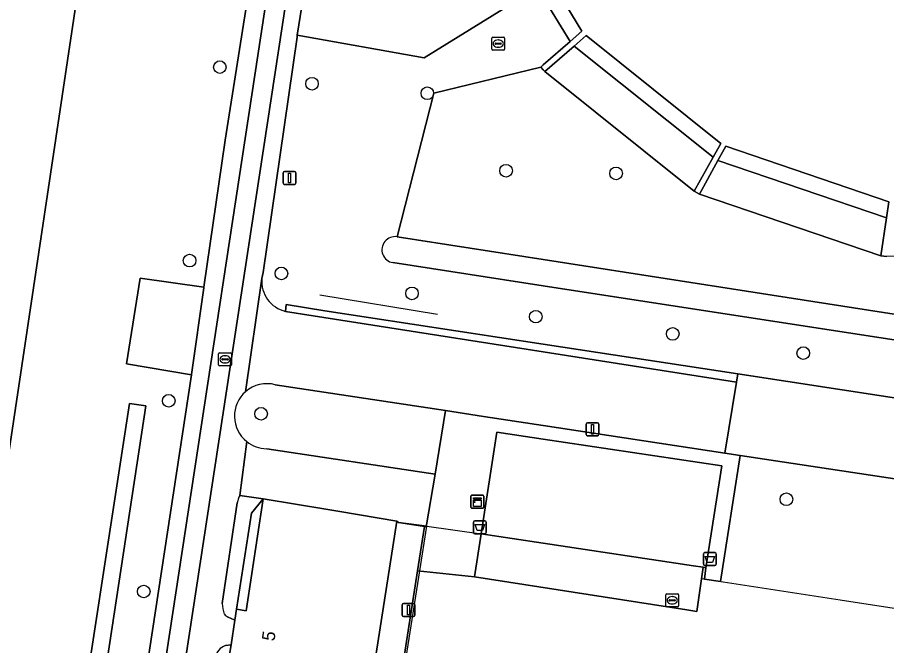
# Model space of a CAD drawing. Extents: x 161090 to 161692, y 379509 to 380907.
# Drawn here: x 161459.2 to 161526.6, y 380261.3 to 380310 of the extents above; entities that cross this region are included whole.
import ezdxf

# ---------------------------------------------------------------- set-up
doc = ezdxf.new("R2010")
doc.units = 0
for name, color, linetype in [('IMGEO_Afvalbak', 7, 'Continuous'), ('IMGEO_Boom', 7, 'Continuous'), ('IMGEO_Greppel_droge_sloot', 7, 'Continuous'), ('IMGEO_Groenvoorziening', 7, 'Continuous'), ('IMGEO_Hek', 7, 'Continuous'), ('IMGEO_Kast', 7, 'Continuous'), ('IMGEO_Lichtmast', 7, 'Continuous'), ('IMGEO_Pand', 7, 'Continuous'), ('IMGEO_Pand_nummerreeks', 7, 'Continuous'), ('IMGEO_Parkeervlak_open', 7, 'Continuous'), ('IMGEO_Rijbaan_lokaal_gesloten', 7, 'Continuous'), ('IMGEO_Rijbaan_lokaal_open', 7, 'Continuous'), ('IMGEO_Rioolput', 7, 'Continuous'), ('IMGEO_Terreindeel_gesloten', 7, 'Continuous'), ('IMGEO_Voetpad_halfverhard', 7, 'Continuous'), ('IMGEO_Voetpad_open', 7, 'Continuous'), ('IMGEO_Waterleidingput', 7, 'Continuous')]:
    doc.layers.add(name, color=color, linetype=linetype)

msp = doc.modelspace()

# ---------------------------------------------------------------- linework, layer by layer
at = {"layer": 'IMGEO_Afvalbak'}
for p, q in [((161494.677, 380270.994), (161495.467, 380270.994)), ((161495.467, 380270.994), (161494.677, 380270.994)), ((161494.577, 380270.094), (161494.577, 380270.894)), ((161494.577, 380270.894), (161494.577, 380270.094)), ((161495.567, 380270.894), (161495.567, 380270.094)), ((161495.567, 380270.094), (161495.567, 380270.894)), ((161495.467, 380269.994), (161494.677, 380269.994)), ((161494.677, 380269.994), (161495.467, 380269.994)), ((161512.428, 380267.629), (161512.428, 380268.429)), ((161512.428, 380268.429), (161512.428, 380267.629)), ((161512.528, 380268.529), (161513.318, 380268.529)), ((161513.318, 380268.529), (161512.528, 380268.529)), ((161513.418, 380268.429), (161513.418, 380267.629)), ((161513.418, 380267.629), (161513.418, 380268.429)), ((161513.318, 380267.529), (161512.528, 380267.529)), ((161512.528, 380267.529), (161513.318, 380267.529))]:
    msp.add_line(p, q, dxfattribs=at)
for points in [[(161494.72, 380270.708), (161495.424, 380270.708), (161495.275, 380270.238), (161494.869, 380270.238), (161494.72, 380270.708)], [(161512.571, 380268.243), (161513.275, 380268.243), (161513.126, 380267.773), (161512.72, 380267.773), (161512.571, 380268.243)]]:
    msp.add_lwpolyline(points, dxfattribs=at)
for centre, start, end in [((161494.677, 380270.894), 90, 180), ((161494.677, 380270.894), 90, 180), ((161495.467, 380270.894), 0, 90), ((161495.467, 380270.894), 360, 90), ((161494.677, 380270.094), 180, 270), ((161494.677, 380270.094), 180, 270), ((161495.467, 380270.094), 270, 0), ((161495.467, 380270.094), 270, 0), ((161512.528, 380268.429), 90, 180), ((161512.528, 380268.429), 90, 180), ((161513.318, 380268.429), 0, 90), ((161513.318, 380268.429), 360, 90), ((161512.528, 380267.629), 180, 270), ((161512.528, 380267.629), 180, 270), ((161513.318, 380267.629), 270, 0), ((161513.318, 380267.629), 270, 0)]:
    msp.add_arc(centre, 0.1, start, end, dxfattribs=at)
at = {"layer": 'IMGEO_Boom'}
for centre in [(161474.898, 380306.17), (161482.053, 380304.882), (161490.999, 380304.148), (161497.111, 380298.137), (161505.645, 380297.93), (161472.554, 380291.168), (161479.68, 380290.173), (161489.81, 380288.629), (161499.416, 380286.823), (161510.042, 380285.49), (161520.172, 380283.997), (161470.934, 380280.302), (161478.097, 380279.294), (161518.864, 380272.671), (161468.994, 380265.516)]:
    msp.add_circle(centre, 0.489, dxfattribs=at)
at = {"layer": 'IMGEO_Greppel_droge_sloot'}
for points in [[(161500, 380291.251), (161488.653, 380293.015)], [(161488.331, 380291.011), (161500, 380289.216), (161574.117, 380277.813), (161575.323, 380279.543), (161566.255, 380280.953), (161500, 380291.251)]]:
    msp.add_lwpolyline(points, dxfattribs=at)
msp.add_lwpolyline([(161469.146, 380279.911), (161467.896, 380280.089), (161463.253, 380250), (161459.495, 380225.647), (161460.876, 380225.356), (161464.612, 380250)], close=True, dxfattribs=at)
msp.add_arc((161488.491, 380292.013), 1.015, 80.8161, 260.92753, dxfattribs=at)
at = {"layer": 'IMGEO_Groenvoorziening'}
for points in [[(161468.714, 380289.805), (161473.666, 380289.12), (161475.319, 380300.52), (161477.293, 380313.127), (161481.572, 380340.98), (161476.723, 380344.754), (161468.564, 380345.931), (161467.674, 380339.759), (161468.027, 380339.705), (161454.566, 380250), (161452.226, 380234.4), (161452.191, 380234.169), (161446.05, 380235.084), (161445.627, 380235.147), (161445.404, 380233.707), (161445.183, 380231.716), (161459.211, 380229.466), (161458.539, 380225.11), (161462.153, 380224.392)], [(161491.515, 380304.148), (161499.803, 380306.171), (161500, 380306.343), (161502.074, 380308.157), (161500, 380311.586), (161499.542, 380312.343), (161490.761, 380306.887), (161480.908, 380308.64), (161480.887, 380308.503), (161478.257, 380290.258), (161478.163, 380289.777)], [(161488.653, 380293.015), (161491.515, 380304.148)], [(161480.007, 380287.232), (161480.042, 380287.763), (161483.038, 380287.288), (161500, 380284.691), (161515.085, 380282.382), (161571.082, 380273.823), (161574.117, 380277.813), (161500, 380289.216), (161488.331, 380291.011)], [(161463.827, 380225.238), (161464.029, 380226.403), (161465.207, 380233.179), (161472.691, 380282.325), (161467.654, 380283.17), (161468.714, 380289.805)], [(161492.398, 380279.538), (161479.202, 380281.544)], [(161478.535, 380276.59), (161491.599, 380274.601), (161492.398, 380279.538)], [(161571.501, 380267.574), (161515.278, 380276.061), (161513.755, 380266.304), (161512.509, 380266.485), (161512.618, 380267.36), (161512.415, 380267.391), (161512.279, 380266.508), (161511.902, 380263.976), (161511.145, 380264.094), (161494.657, 380266.645), (161490.25, 380267.131), (161487.578, 380250), (161486.942, 380245.925), (161484.775, 380246.307), (161476.761, 380247.535), (161466.509, 380179.329)], [(161476.248, 380272.398), (161475.082, 380264.596)], [(161477.368, 380271.592), (161478.255, 380272.694), (161476.447, 380272.956)], [(161475.555, 380263.529), (161476.007, 380263.315), (161476.066, 380263.282), (161476.2, 380264.154), (161477.368, 380271.592)], [(161474.092, 380248.508), (161473.892, 380248.836), (161475.658, 380260.635), (161475.772, 380261.375), (161475.343, 380261.323)]]:
    msp.add_lwpolyline(points, dxfattribs=at)
for points in [[(161513.173, 380299.178), (161502.387, 380307.807), (161500.116, 380305.828), (161511.708, 380296.554)], [(161541.506, 380291.776), (161526.645, 380291.478), (161526.188, 380291.549), (161512.11, 380296.325), (161511.708, 380296.554), (161500.116, 380305.828), (161500, 380305.955), (161499.803, 380306.171), (161491.515, 380304.148), (161488.653, 380293.015), (161500, 380291.251), (161566.255, 380280.953), (161556.212, 380297.498), (161555.81, 380297.247), (161541.96, 380291.864)], [(161526.632, 380294.498), (161513.542, 380298.93), (161512.11, 380296.325), (161526.188, 380291.549)], [(161515.085, 380282.382), (161500, 380284.691), (161483.038, 380287.288), (161480.042, 380287.763), (161480.007, 380287.232), (161500, 380284.102), (161514.984, 380281.757)], [(161463.253, 380250), (161467.896, 380280.089), (161469.146, 380279.911), (161464.612, 380250), (161460.876, 380225.356), (161459.495, 380225.647)], [(161478.255, 380272.694), (161477.368, 380271.592), (161476.2, 380264.154), (161476.94, 380264.03)]]:
    msp.add_lwpolyline(points, close=True, dxfattribs=at)
for centre, radius, start, end in [((161488.491, 380292.013), 1.015, 80.8161, 260.92753), ((161480.546, 380289.563), 2.393, 174.87056, 256.98046), ((161478.553, 380279.11), 2.519, 75.08028, 131.20974), ((161478.554, 380279.11), 2.519, 131.2084, 231.40089), ((161478.555, 380279.109), 2.519, 231.3763, 269.55462), ((161478.34, 380271.966), 2.136, 152.40098, 168.34342), ((161477.584, 380264.669), 2.503, 181.6754, 201.05116), ((161475.707, 380264.038), 0.531, 210.32108, 253.41394), ((161475.716, 380260.18), 1.202, 108.0641, 168.98902)]:
    msp.add_arc(centre, radius, start, end, dxfattribs=at)
at = {"layer": 'IMGEO_Hek'}
for points in [[(161467.654, 380283.17), (161468.714, 380289.805)], [(161482.653, 380288.518), (161491.78, 380287.023)], [(161487.042, 380245.645), (161490.407, 380267.114), (161490.951, 380270.588)], [(161490.951, 380270.588), (161488.77, 380270.861)], [(161490.951, 380270.588), (161495.182, 380269.995)], [(161512.279, 380266.508), (161512.415, 380267.391)], [(161574.717, 380256.895), (161523.039, 380264.851), (161512.279, 380266.508)], [(161512.509, 380266.485), (161513.755, 380266.304)]]:
    msp.add_lwpolyline(points, dxfattribs=at)
at = {"layer": 'IMGEO_Kast'}
for p, q in [((161494.376, 380272.058), (161494.376, 380272.899)), ((161494.376, 380272.899), (161494.376, 380272.058)), ((161494.451, 380272.983), (161495.292, 380272.983)), ((161495.292, 380272.983), (161494.451, 380272.983)), ((161495.376, 380272.908), (161495.376, 380272.067)), ((161495.376, 380272.067), (161495.376, 380272.908)), ((161495.301, 380271.983), (161494.46, 380271.983)), ((161494.46, 380271.983), (161495.301, 380271.983))]:
    msp.add_line(p, q, dxfattribs=at)
for points in [[(161494.571, 380272.773), (161495.171, 380272.773), (161495.171, 380272.688), (161494.571, 380272.688), (161494.571, 380272.773)], [(161494.571, 380272.598), (161495.171, 380272.598), (161495.171, 380272.109), (161494.571, 380272.109), (161494.571, 380272.598)]]:
    msp.add_lwpolyline(points, dxfattribs=at)
msp.add_circle((161494.655, 380272.447), 0.0377, dxfattribs=at)
for centre, start, end in [((161494.454, 380272.905), 92.4484, 184.28452), ((161494.454, 380272.905), 92.4484, 184.28452), ((161495.298, 380272.905), 2.4484, 94.28452), ((161495.298, 380272.905), 2.4484, 94.28452), ((161494.454, 380272.061), 182.4484, 274.28452), ((161494.454, 380272.061), 182.4484, 274.28452), ((161495.298, 380272.061), 272.4484, 4.28452), ((161495.298, 380272.061), 272.4484, 4.28452)]:
    msp.add_arc(centre, 0.0779, start, end, dxfattribs=at)
at = {"layer": 'IMGEO_Lichtmast'}
for p, q in [((161479.813, 380297.181), (161479.813, 380297.981)), ((161479.813, 380297.981), (161479.813, 380297.181)), ((161479.913, 380298.081), (161480.703, 380298.081)), ((161480.703, 380298.081), (161479.913, 380298.081)), ((161480.803, 380297.981), (161480.803, 380297.181)), ((161480.803, 380297.181), (161480.803, 380297.981)), ((161480.703, 380297.081), (161479.913, 380297.081)), ((161479.913, 380297.081), (161480.703, 380297.081)), ((161503.324, 380277.697), (161503.324, 380278.497)), ((161503.324, 380278.497), (161503.324, 380277.697)), ((161503.424, 380278.597), (161504.214, 380278.597)), ((161504.214, 380278.597), (161503.424, 380278.597)), ((161504.314, 380278.497), (161504.314, 380277.697)), ((161504.314, 380277.697), (161504.314, 380278.497)), ((161504.214, 380277.597), (161503.424, 380277.597)), ((161503.424, 380277.597), (161504.214, 380277.597)), ((161489.041, 380263.687), (161489.041, 380264.487)), ((161489.041, 380264.487), (161489.041, 380263.687)), ((161489.141, 380264.587), (161489.931, 380264.587)), ((161489.931, 380264.587), (161489.141, 380264.587)), ((161490.031, 380264.487), (161490.031, 380263.687)), ((161490.031, 380263.687), (161490.031, 380264.487)), ((161489.931, 380263.587), (161489.141, 380263.587)), ((161489.141, 380263.587), (161489.931, 380263.587))]:
    msp.add_line(p, q, dxfattribs=at)
for points in [[(161480.233, 380297.956), (161480.383, 380297.956), (161480.383, 380297.206), (161480.233, 380297.206), (161480.233, 380297.956)], [(161503.744, 380278.472), (161503.894, 380278.472), (161503.894, 380277.722), (161503.744, 380277.722), (161503.744, 380278.472)], [(161489.461, 380264.462), (161489.611, 380264.462), (161489.611, 380263.712), (161489.461, 380263.712), (161489.461, 380264.462)]]:
    msp.add_lwpolyline(points, dxfattribs=at)
for centre, start, end in [((161479.913, 380297.981), 90, 180), ((161479.913, 380297.981), 90, 180), ((161480.703, 380297.981), 0, 90), ((161480.703, 380297.981), 360, 90), ((161479.913, 380297.181), 180, 270), ((161479.913, 380297.181), 180, 270), ((161480.703, 380297.181), 270, 0), ((161480.703, 380297.181), 270, 0), ((161503.424, 380278.497), 90, 180), ((161503.424, 380278.497), 90, 180), ((161504.214, 380278.497), 0, 90), ((161504.214, 380278.497), 360, 90), ((161503.424, 380277.697), 180, 270), ((161503.424, 380277.697), 180, 270), ((161504.214, 380277.697), 270, 0), ((161504.214, 380277.697), 270, 0), ((161489.141, 380264.487), 90, 180), ((161489.141, 380264.487), 90, 180), ((161489.931, 380264.487), 0, 90), ((161489.931, 380264.487), 360, 90), ((161489.141, 380263.687), 180, 270), ((161489.141, 380263.687), 180, 270), ((161489.931, 380263.687), 270, 0), ((161489.931, 380263.687), 270, 0)]:
    msp.add_arc(centre, 0.1, start, end, dxfattribs=at)
at = {"layer": 'IMGEO_Pand'}
for points in [[(161454.566, 380250), (161468.027, 380339.705), (161467.674, 380339.759), (161462.242, 380340.585), (161461.477, 380340.701), (161461.676, 380342.209), (161460.497, 380342.387), (161460.282, 380340.917), (161460.165, 380340.92), (161458.225, 380327.954)], [(161500, 380313.923), (161502.996, 380308.963), (161502.074, 380308.157), (161500, 380306.343), (161499.803, 380306.171), (161500, 380305.955), (161500.116, 380305.828), (161502.387, 380307.807), (161503.318, 380308.619), (161513.77, 380300.246), (161513.173, 380299.178), (161511.708, 380296.554), (161512.11, 380296.325), (161513.542, 380298.93), (161514.158, 380300.051), (161526.819, 380295.736), (161526.632, 380294.498), (161526.188, 380291.549), (161526.645, 380291.478)]]:
    msp.add_lwpolyline(points, dxfattribs=at)
for points in [[(161513.842, 380275.25), (161500, 380277.328), (161496.387, 380277.87), (161495.182, 380269.995), (161500, 380269.267), (161511.66, 380267.505), (161512.415, 380267.391), (161512.618, 380267.36)], [(161488.622, 380270.98), (161484.207, 380271.71), (161483.281, 380271.863), (161478.255, 380272.694), (161476.94, 380264.03), (161476.2, 380264.154), (161476.066, 380263.282), (161475.772, 380261.375), (161475.658, 380260.635), (161476.425, 380260.498), (161474.472, 380247.886), (161476.294, 380247.607), (161476.761, 380247.535), (161484.775, 380246.307)]]:
    msp.add_lwpolyline(points, close=True, dxfattribs=at)
at = {"layer": 'IMGEO_Parkeervlak_open'}
msp.add_lwpolyline([(161473.656, 380289.049), (161473.666, 380289.12), (161468.714, 380289.805), (161467.654, 380283.17), (161472.691, 380282.325), (161472.695, 380282.352)], close=True, dxfattribs=at)
at = {"layer": 'IMGEO_Rijbaan_lokaal_gesloten'}
for points in [[(161456.074, 380164.596), (161466.094, 380230.202), (161483.979, 380347.225)], [(161485.505, 380347.041), (161467.599, 380229.99), (161457.567, 380164.364)], [(161477.293, 380313.127), (161475.319, 380300.52), (161473.666, 380289.12), (161473.656, 380289.049), (161472.695, 380282.352), (161472.691, 380282.325), (161465.207, 380233.179), (161464.029, 380226.403), (161463.827, 380225.238), (161462.538, 380217.249), (161462.38, 380216.189), (161457.863, 380185.825)], [(161480.887, 380308.503), (161480.908, 380308.64), (161481.485, 380312.377)], [(161476.894, 380281.005), (161478.163, 380289.777), (161478.257, 380290.258), (161480.887, 380308.503)], [(161478.163, 380289.777), (161476.894, 380281.005)], [(161500, 380284.102), (161480.007, 380287.232)], [(161479.202, 380281.544), (161492.398, 380279.538), (161495.36, 380279.088), (161500, 380278.383), (161514.092, 380276.241), (161514.984, 380281.757), (161500, 380284.102)], [(161476.447, 380272.956), (161476.982, 380277.141)], [(161475.082, 380264.596), (161476.248, 380272.398)], [(161475.343, 380261.323), (161475.772, 380261.375), (161476.066, 380263.282), (161476.007, 380263.315), (161475.555, 380263.529)]]:
    msp.add_lwpolyline(points, dxfattribs=at)
for centre, radius, start, end in [((161480.546, 380289.563), 2.393, 174.87056, 256.98046), ((161478.553, 380279.11), 2.519, 75.08028, 131.20974), ((161478.554, 380279.11), 2.519, 131.2084, 231.40089), ((161478.34, 380271.966), 2.136, 152.40098, 168.34342), ((161477.584, 380264.669), 2.503, 181.6754, 201.05116), ((161475.707, 380264.038), 0.531, 210.32108, 253.41394), ((161475.716, 380260.18), 1.202, 108.0641, 168.98902)]:
    msp.add_arc(centre, radius, start, end, dxfattribs=at)
at = {"layer": 'IMGEO_Rijbaan_lokaal_open'}
for points in [[(161496.967, 380422.687), (161497.303, 380424.898), (161498.535, 380426.719), (161500.797, 380441.248), (161501.473, 380445.586), (161499.017, 380445.989), (161498.373, 380441.757), (161495.524, 380423.042), (161485.861, 380359.57), (161485.809, 380359.378), (161483.979, 380347.225), (161466.094, 380230.202), (161456.074, 380164.596), (161457.567, 380164.364), (161467.599, 380229.99), (161485.505, 380347.041), (161487.307, 380359.083), (161487.325, 380359.344)], [(161515.085, 380282.382), (161514.984, 380281.757), (161514.092, 380276.241), (161515.278, 380276.061), (161571.501, 380267.574), (161576.918, 380266.95), (161578.015, 380271.799), (161578.015, 380277.213), (161574.117, 380277.813), (161571.082, 380273.823)]]:
    msp.add_lwpolyline(points, close=True, dxfattribs=at)
at = {"layer": 'IMGEO_Rioolput'}
for p, q in [((161495.997, 380307.57), (161495.997, 380308.422)), ((161496.072, 380308.496), (161496.924, 380308.496)), ((161496.485, 380308.276), (161496.51, 380308.276)), ((161496.998, 380308.422), (161496.998, 380307.57)), ((161496.924, 380307.496), (161496.072, 380307.496)), ((161496.256, 380307.99), (161496.256, 380308.002)), ((161496.694, 380307.953), (161496.296, 380307.953)), ((161496.299, 380308.039), (161496.697, 380308.039)), ((161496.508, 380307.716), (161496.483, 380307.716)), ((161496.74, 380308.002), (161496.74, 380307.99)), ((161474.808, 380283.087), (161474.808, 380283.939)), ((161474.883, 380284.013), (161475.735, 380284.013)), ((161475.809, 380283.939), (161475.809, 380283.087)), ((161475.067, 380283.507), (161475.067, 380283.519)), ((161475.505, 380283.47), (161475.107, 380283.47)), ((161475.11, 380283.556), (161475.508, 380283.556)), ((161475.319, 380283.233), (161475.294, 380283.233)), ((161475.296, 380283.793), (161475.321, 380283.793)), ((161475.551, 380283.519), (161475.551, 380283.507)), ((161475.735, 380283.013), (161474.883, 380283.013))]:
    msp.add_line(p, q, dxfattribs=at)
for points in [[(161495.997, 380307.57), (161495.997, 380308.422)], [(161496.072, 380308.496), (161496.924, 380308.496)], [(161496.998, 380308.422), (161496.998, 380307.57)], [(161496.924, 380307.496), (161496.072, 380307.496)], [(161474.808, 380283.087), (161474.808, 380283.939)], [(161474.883, 380284.013), (161475.735, 380284.013)], [(161475.809, 380283.939), (161475.809, 380283.087)], [(161475.735, 380283.013), (161474.883, 380283.013)]]:
    msp.add_lwpolyline(points, dxfattribs=at)
for centre, radius, start, end in [((161496.074, 380308.42), 0.0765, 91.55205, 178.44795), ((161496.074, 380308.42), 0.0765, 91.55205, 178.44795), ((161496.922, 380308.42), 0.0765, 1.55205, 88.44795), ((161496.922, 380308.42), 0.0765, 1.55205, 88.44795), ((161496.074, 380307.572), 0.0765, 181.55205, 268.44795), ((161496.074, 380307.572), 0.0765, 181.55205, 268.44795), ((161496.296, 380307.999), 0.0403, 85.87752, 175.75265), ((161496.293, 380307.989), 0.0366, 178.93798, 274.71019), ((161496.697, 380307.996), 0.043, 264.86636, 352.45326), ((161496.701, 380308.001), 0.0386, 1.73085, 96.63898), ((161496.922, 380307.572), 0.0765, 271.55205, 358.44795), ((161496.922, 380307.572), 0.0765, 271.55205, 358.44795), ((161474.885, 380283.937), 0.0765, 91.55205, 178.44795), ((161474.885, 380283.937), 0.0765, 91.55205, 178.44795), ((161475.733, 380283.937), 0.0765, 1.55205, 88.44795), ((161475.733, 380283.937), 0.0765, 1.55205, 88.44795), ((161475.107, 380283.516), 0.0403, 85.87752, 175.75265), ((161475.104, 380283.506), 0.0366, 178.93798, 274.71019), ((161475.508, 380283.513), 0.043, 264.86636, 352.45326), ((161475.512, 380283.518), 0.0386, 1.73085, 96.63898), ((161474.885, 380283.089), 0.0765, 181.55205, 268.44795), ((161474.885, 380283.089), 0.0765, 181.55205, 268.44795), ((161475.733, 380283.089), 0.0765, 271.55205, 358.44795), ((161475.733, 380283.089), 0.0765, 271.55205, 358.44795)]:
    msp.add_arc(centre, radius, start, end, dxfattribs=at)
for centre, major_axis, ratio, start_param, end_param in [((161496.484, 380307.996), (-0.387, 0.002), 0.722429, 4.712389, 7.853982), ((161496.509, 380307.996), (-0.39, 0.002), 0.717154, 1.570796, 4.712389), ((161475.295, 380283.513), (-0.387, 0.002), 0.722429, 4.712389, 7.853982), ((161475.32, 380283.513), (-0.39, 0.002), 0.717154, 1.570796, 4.712389)]:
    msp.add_ellipse(centre, major_axis=major_axis, ratio=ratio, start_param=start_param, end_param=end_param, dxfattribs=at)
at = {"layer": 'IMGEO_Terreindeel_gesloten'}
msp.add_lwpolyline([(161512.415, 380267.391), (161511.66, 380267.505), (161500, 380269.267), (161495.182, 380269.995), (161494.657, 380266.645), (161511.145, 380264.094), (161511.902, 380263.976), (161512.279, 380266.508)], close=True, dxfattribs=at)
at = {"layer": 'IMGEO_Voetpad_halfverhard'}
for points in [[(161476.982, 380277.141), (161476.447, 380272.956), (161478.255, 380272.694), (161483.281, 380271.863), (161484.207, 380271.71), (161488.622, 380270.98), (161488.77, 380270.861), (161490.783, 380270.549), (161490.897, 380270.531), (161491.599, 380274.601)], [(161491.599, 380274.601), (161478.535, 380276.59)]]:
    msp.add_lwpolyline(points, dxfattribs=at)
msp.add_arc((161478.555, 380279.109), 2.519, 231.3763, 269.55462, dxfattribs=at)
at = {"layer": 'IMGEO_Voetpad_open'}
for points in [[(161499.542, 380312.343), (161500, 380311.586), (161502.074, 380308.157), (161502.996, 380308.963), (161500, 380313.923), (161498.471, 380316.454), (161496.069, 380320.431), (161494.951, 380319.996), (161497.448, 380315.827), (161489.527, 380310.973), (161481.485, 380312.377), (161480.908, 380308.64), (161490.761, 380306.887)], [(161513.173, 380299.178), (161513.77, 380300.246), (161503.318, 380308.619), (161502.387, 380307.807)], [(161526.632, 380294.498), (161526.819, 380295.736), (161514.158, 380300.051), (161513.542, 380298.93)], [(161496.387, 380277.87), (161500, 380277.328), (161513.842, 380275.25), (161512.618, 380267.36), (161512.509, 380266.485), (161513.755, 380266.304), (161515.278, 380276.061), (161514.092, 380276.241), (161500, 380278.383), (161495.36, 380279.088), (161492.398, 380279.538), (161491.599, 380274.601), (161490.897, 380270.531), (161490.783, 380270.549), (161490.25, 380267.131), (161494.657, 380266.645), (161495.182, 380269.995)], [(161490.25, 380267.131), (161490.783, 380270.549), (161488.77, 380270.861), (161488.622, 380270.98), (161484.775, 380246.307), (161486.942, 380245.925), (161487.578, 380250)]]:
    msp.add_lwpolyline(points, close=True, dxfattribs=at)
at = {"layer": 'IMGEO_Waterleidingput'}
for p, q in [((161509.5, 380264.412), (161509.5, 380265.264)), ((161509.575, 380265.338), (161510.427, 380265.338)), ((161509.988, 380265.118), (161510.013, 380265.118)), ((161510.501, 380265.264), (161510.501, 380264.412)), ((161510.427, 380264.338), (161509.575, 380264.338)), ((161509.759, 380264.832), (161509.759, 380264.844)), ((161510.197, 380264.795), (161509.799, 380264.795)), ((161509.802, 380264.881), (161510.2, 380264.881)), ((161510.011, 380264.558), (161509.986, 380264.558)), ((161510.243, 380264.844), (161510.243, 380264.832))]:
    msp.add_line(p, q, dxfattribs=at)
for points in [[(161509.5, 380264.412), (161509.5, 380265.264)], [(161509.575, 380265.338), (161510.427, 380265.338)], [(161510.501, 380265.264), (161510.501, 380264.412)], [(161510.427, 380264.338), (161509.575, 380264.338)]]:
    msp.add_lwpolyline(points, dxfattribs=at)
for centre, radius, start, end in [((161509.577, 380265.262), 0.0765, 91.55205, 178.44795), ((161509.577, 380265.262), 0.0765, 91.55205, 178.44795), ((161510.425, 380265.262), 0.0765, 1.55205, 88.44795), ((161510.425, 380265.262), 0.0765, 1.55205, 88.44795), ((161509.577, 380264.414), 0.0765, 181.55205, 268.44795), ((161509.577, 380264.414), 0.0765, 181.55205, 268.44795), ((161509.799, 380264.841), 0.0403, 85.87752, 175.75265), ((161509.796, 380264.831), 0.0366, 178.93798, 274.71019), ((161510.2, 380264.838), 0.043, 264.86636, 352.45326), ((161510.204, 380264.843), 0.0386, 1.73085, 96.63898), ((161510.425, 380264.414), 0.0765, 271.55205, 358.44795), ((161510.425, 380264.414), 0.0765, 271.55205, 358.44795)]:
    msp.add_arc(centre, radius, start, end, dxfattribs=at)
for centre, major_axis, ratio, start_param, end_param in [((161509.987, 380264.838), (-0.387, 0.002), 0.722429, 4.712389, 7.853982), ((161510.012, 380264.838), (-0.39, 0.002), 0.717154, 1.570796, 4.712389)]:
    msp.add_ellipse(centre, major_axis=major_axis, ratio=ratio, start_param=start_param, end_param=end_param, dxfattribs=at)

# ---------------------------------------------------------------- texts
at = {"layer": 'IMGEO_Pand_nummerreeks'}
msp.add_text('5', height=1, rotation=81.24542, dxfattribs=at).set_placement((161479.129, 380261.626))

doc.saveas('drawing.dxf')
